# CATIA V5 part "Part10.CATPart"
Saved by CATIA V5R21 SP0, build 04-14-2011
Part number: Tole_trappe
Bounding box of the stored display mesh (mm): x 0 to 2, y -106 to 105.998, z -38.134 to 25.883
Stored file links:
  C:\Users\zerma\Pictures\Stage Stomate\Part10.CATPart
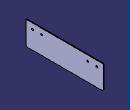
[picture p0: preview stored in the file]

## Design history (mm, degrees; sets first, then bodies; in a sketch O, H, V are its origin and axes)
Body1 (main body)
  DatumCurve1 to DatumCurve7
  Sketch1 on yz-plane, origin (0, 0, 0), H (0, 1, 0), V (0, 0, 1)
    line L1 (105.9982, 25.8831) -> (105.9982, -38.1169)
    line L2 (105.9982, -38.1169) -> (-105.995, -38.135)
    line L3 (-105.995, -38.135) -> (-106.0004, 25.8831)
    line L4 (-106.0004, 25.8831) -> (105.9982, 25.8831)
    circle A1 centre (87.9982, 10.8831) radius 2.5
    point P5 (87.9982, 10.8831)
    circle A2 centre (62.9982, 10.8831) radius 2.5
    point P6 (62.9982, 10.8831)
    reference projected line E1 (-105.9955, -32.135) -> (-106.0004, 25.8649) from edge of DatumCurve6
    reference projected line E2 (100.005, -38.1174) -> (-99.995, -38.1345) from edge of DatumCurve7
    circle A3 centre (-87.9982, 10.8831) radius 2.5
    circle A4 centre (-62.9982, 10.8831) radius 2.5
    length L1 = 64
    radius A1 = 2.5
    radius A2 = 2.5
    length L2 = 211.9932
    distance P5 L4 = 15
    distance P5 P6 = 25
    distance P6 L4 = 15
    distance P5 L1 = 18
    vertical: L1 V
    horizontal: L4 H
    coincidence: L3 E1, L2 E2
    symmetry: A1 A3 V, A2 A4 V
  Pad1: profile Sketch1, direction (1, 0, 0), length 2
  DatumSurface1
  Fillet1: radius 6, on edge [face of Pad1 from Sketch1.L1 | face of Pad1 from Sketch1.L2]; edge [face of Pad1 from Sketch1.L2 | face of Pad1 from Sketch1.L3]
  Sketch2 on face of DatumSurface1, origin (0, 0, 0), H (0, -1, 0), V (0, 0, 1)
    circle A1 centre (62.9982, 10.8831) radius 2.5
    reference projected circle E1 centre (62.9982, 10.8831) radius 2.5 from edge [end face of Pad1 | face of Pad1 from Sketch1.A4]
    reference projected circle E2 centre (62.9982, 10.8831) radius 2.5 from edge [end face of Pad1 | face of Pad1 from Sketch1.A4]
    circle A2 centre (87.9982, 10.8831) radius 2.5
    reference projected circle E3 centre (87.9982, 10.8831) radius 2.5 from edge [end face of Pad1 | face of Pad1 from Sketch1.A3]
    reference projected circle E4 centre (87.9982, 10.8831) radius 2.5 from edge [end face of Pad1 | face of Pad1 from Sketch1.A3]
    concentricity: A1 E1, A2 E4
    coincidence: A1 E2, A2 E3
  Pocket1: profile Sketch2, direction (-1, 0, 0), length 5, outer side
